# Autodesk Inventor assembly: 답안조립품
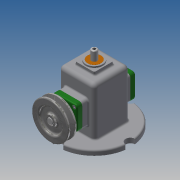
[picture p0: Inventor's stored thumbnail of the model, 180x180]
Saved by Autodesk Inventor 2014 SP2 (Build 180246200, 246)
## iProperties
Created: 2018-07
Part Number: 답안조립품
Document SubType Name: Assembly
Designer: cm
Author: cm
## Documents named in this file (16)
- C:\Users\cm\Desktop\480707V1013\답안조립품.iam
- C:\Users\cm\Desktop\480707V1013\본체.ipt
- C:\Users\cm\Desktop\480707V1013\뒤커버.ipt
- C:\Users\cm\Desktop\480707V1013\앞커버.ipt
- C:\Users\cm\Desktop\480707V1013\베어링 12x32x10.ipt
- C:\Users\cm\Desktop\480707V1013\편심축.ipt
- C:\Users\cm\Desktop\480707V1013\오일 실 12 25 7.ipt
- C:\Users\cm\Desktop\480707V1013\링크.ipt
- C:\Users\cm\Desktop\480707V1013\슬라이드.ipt
- C:\Users\cm\Desktop\480707V1013\핀 5x18.ipt
- C:\Users\cm\Desktop\480707V1013\부시.ipt
- C:\Users\cm\Desktop\480707V1013\고정핀 1.2x8.ipt
- C:\Users\cm\Desktop\480707V1013\키 4x4x10.ipt
- C:\Users\cm\Desktop\480707V1013\V벨트풀리.ipt
- C:\Users\cm\Desktop\480707V1013\볼트 M4.ipt
- C:\Users\cm\Desktop\480707V1013\멈춤나사 M3x8.ipt
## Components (3 placed, 3 different names)
1. 핀 5x18:1
2. 고정핀 1.2x8:1
3. V벨트풀리:1
